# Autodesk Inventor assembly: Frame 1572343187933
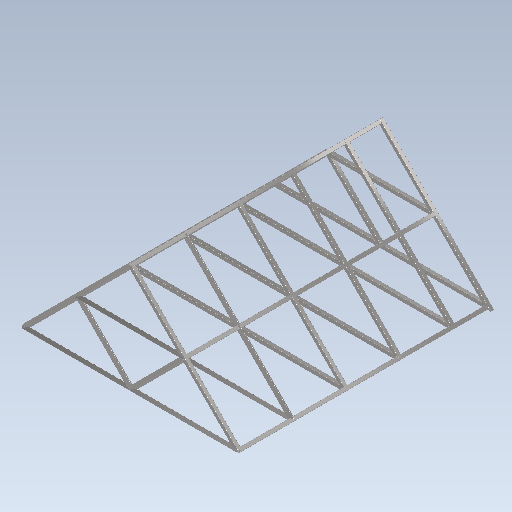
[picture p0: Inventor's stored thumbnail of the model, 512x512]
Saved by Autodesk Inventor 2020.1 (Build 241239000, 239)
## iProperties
_FrameDoc: Frame Assembly
_Version: 15.0.0
Created: 2019-10
Part Number: Frame 1572343187933
Document SubType Name: Assembly
Designer: Synergysoft Dell02
Author: Synergysoft Dell02
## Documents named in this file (31)
- C:\Users\Synergysoft Dell02\Desktop\INV-01 Intro to Modeling_2020\FRAME\Frame\Frame\Frame 1572343187933.iam
- C:\Users\Synergysoft Dell02\Desktop\INV-01 Intro to Modeling_2020\FRAME\Frame\Frame\Skeleton 1572343187934.ipt
- C:\Users\Synergysoft Dell02\Desktop\INV-01 Intro to Modeling_2020\FRAME\Frame\Frame\ISO 100x100x4 1572343189715.ipt
- C:\Users\Synergysoft Dell02\Desktop\INV-01 Intro to Modeling_2020\FRAME\Frame\Frame\ISO 100x100x4 1572343189716.ipt
- C:\Users\Synergysoft Dell02\Desktop\INV-01 Intro to Modeling_2020\FRAME\Frame\Frame\ISO 100x100x4 1572343189717.ipt
- C:\Users\Synergysoft Dell02\Desktop\INV-01 Intro to Modeling_2020\FRAME\Frame\Frame\ISO 100x100x4 1572343189718.ipt
- C:\Users\Synergysoft Dell02\Desktop\INV-01 Intro to Modeling_2020\FRAME\Frame\Frame\ISO 100x100x4 1572343189719.ipt
- C:\Users\Synergysoft Dell02\Desktop\INV-01 Intro to Modeling_2020\FRAME\Frame\Frame\ISO 100x100x4 1572343189720.ipt
- C:\Users\Synergysoft Dell02\Desktop\INV-01 Intro to Modeling_2020\FRAME\Frame\Frame\ISO 100x100x4 1572343189721.ipt
- C:\Users\Synergysoft Dell02\Desktop\INV-01 Intro to Modeling_2020\FRAME\Frame\Frame\ISO 100x100x4 1572343189722.ipt
- C:\Users\Synergysoft Dell02\Desktop\INV-01 Intro to Modeling_2020\FRAME\Frame\Frame\ISO 100x100x4 1572343189723.ipt
- C:\Users\Synergysoft Dell02\Desktop\INV-01 Intro to Modeling_2020\FRAME\Frame\Frame\ISO 100x100x4 1572343189724.ipt
- C:\Users\Synergysoft Dell02\Desktop\INV-01 Intro to Modeling_2020\FRAME\Frame\Frame\ISO 100x100x4 1572343189725.ipt
- C:\Users\Synergysoft Dell02\Desktop\INV-01 Intro to Modeling_2020\FRAME\Frame\Frame\ISO 100x100x4 1572343189726.ipt
- C:\Users\Synergysoft Dell02\Desktop\INV-01 Intro to Modeling_2020\FRAME\Frame\Frame\ISO 100x100x4 1572343189727.ipt
- C:\Users\Synergysoft Dell02\Desktop\INV-01 Intro to Modeling_2020\FRAME\Frame\Frame\ISO 100x100x4 1572343189728.ipt
- C:\Users\Synergysoft Dell02\Desktop\INV-01 Intro to Modeling_2020\FRAME\Frame\Frame\ISO 100x100x4 1572343189729.ipt
- C:\Users\Synergysoft Dell02\Desktop\INV-01 Intro to Modeling_2020\FRAME\Frame\Frame\ISO 100x100x4 1572343189730.ipt
- C:\Users\Synergysoft Dell02\Desktop\INV-01 Intro to Modeling_2020\FRAME\Frame\Frame\ISO 100x100x4 1572343189731.ipt
- C:\Users\Synergysoft Dell02\Desktop\INV-01 Intro to Modeling_2020\FRAME\Frame\Frame\ISO 100x100x4 1572343189732.ipt
- C:\Users\Synergysoft Dell02\Desktop\INV-01 Intro to Modeling_2020\FRAME\Frame\Frame\ISO 100x100x4 1572343189733.ipt
- C:\Users\Synergysoft Dell02\Desktop\INV-01 Intro to Modeling_2020\FRAME\Frame\Frame\ISO 100x100x4 1572343189734.ipt
- C:\Users\Synergysoft Dell02\Desktop\INV-01 Intro to Modeling_2020\FRAME\Frame\Frame\ISO 100x100x4 1572343189735.ipt
- C:\Users\Synergysoft Dell02\Desktop\INV-01 Intro to Modeling_2020\FRAME\Frame\Frame\ISO 100x100x4 1572343189736.ipt
- C:\Users\Synergysoft Dell02\Desktop\INV-01 Intro to Modeling_2020\FRAME\Frame\Frame\ISO 100x100x4 1572343189737.ipt
- C:\Users\Synergysoft Dell02\Desktop\INV-01 Intro to Modeling_2020\FRAME\Frame\Frame\ISO 100x100x4 1572343189738.ipt
- C:\Users\Synergysoft Dell02\Desktop\INV-01 Intro to Modeling_2020\FRAME\Frame\Frame\ISO 100x100x4 1572343189739.ipt
- C:\Users\Synergysoft Dell02\Desktop\INV-01 Intro to Modeling_2020\FRAME\Frame\Frame\ISO 100x100x4 1572343189740.ipt
- C:\Users\Synergysoft Dell02\Desktop\INV-01 Intro to Modeling_2020\FRAME\Frame\Frame\ISO 100x100x4 1572343189741.ipt
- C:\Users\Synergysoft Dell02\Desktop\INV-01 Intro to Modeling_2020\FRAME\Frame\Frame\ISO 100x100x4 1572343189742.ipt
- C:\Users\Synergysoft Dell02\Desktop\INV-01 Intro to Modeling_2020\FRAME\Frame\Frame\ISO 100x100x4 1572343189743.ipt
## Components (30 placed, 2 different names)
1. Frame Reference Model
2. ISO 100x100x4:1
3. ISO 100x100x4:2
4. ISO 100x100x4:3
5. ISO 100x100x4:4
6. ISO 100x100x4:5
7. ISO 100x100x4:6
8. ISO 100x100x4:7
9. ISO 100x100x4:8
10. ISO 100x100x4:9
11. ISO 100x100x4:10
12. ISO 100x100x4:11
13. ISO 100x100x4:12
14. ISO 100x100x4:13
15. ISO 100x100x4:14
16. ISO 100x100x4:15
17. ISO 100x100x4:16
18. ISO 100x100x4:17
19. ISO 100x100x4:18
20. ISO 100x100x4:19
21. ISO 100x100x4:20
22. ISO 100x100x4:21
23. ISO 100x100x4:22
24. ISO 100x100x4:23
25. ISO 100x100x4:24
26. ISO 100x100x4:25
27. ISO 100x100x4:26
28. ISO 100x100x4:27
29. ISO 100x100x4:28
30. ISO 100x100x4:29
